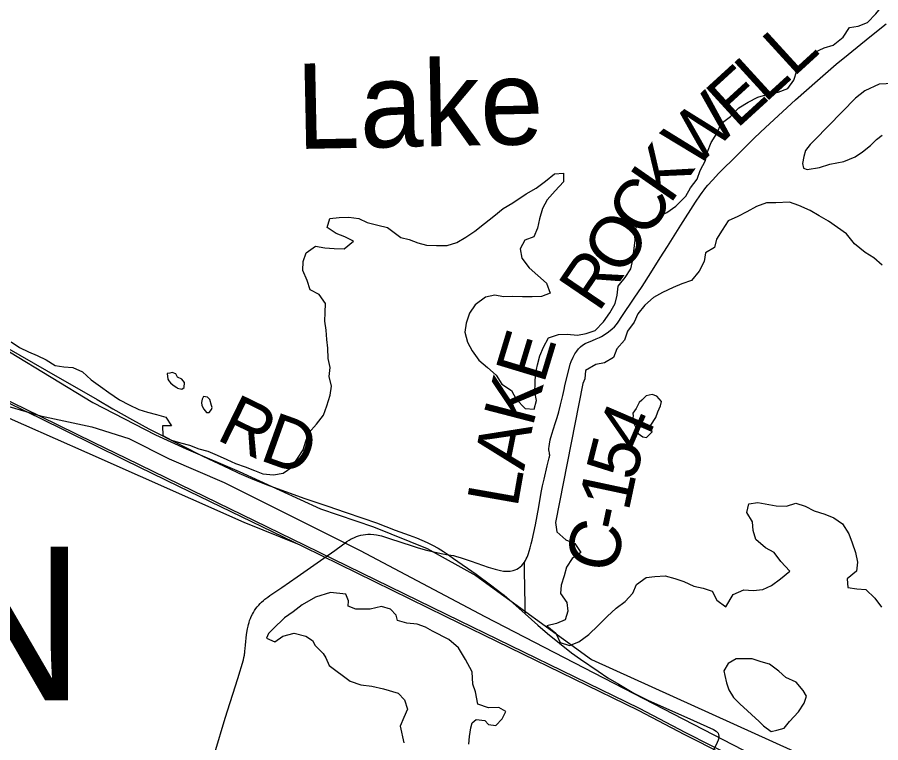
# Model space of a CAD drawing. Extents: x 0 to 34, y 0 to 22.
# Drawn here: x 3.589 to 4.548, y 15.41 to 16.216 of the extents above; entities that cross this region are included whole.
import ezdxf

# ---------------------------------------------------------------- set-up
doc = ezdxf.new("R2010")
doc.units = 0
for name, color, linetype in [('GM_X_County_Road', 7, 'Continuous'), ('GM_X_County_Road_Text', 7, 'Continuous'), ('GM_X_Major_Lake', 7, 'Continuous'), ('GM_X_Major_Lake_Text', 7, 'Continuous'), ('GM_X_Minor_Lake', 7, 'Continuous'), ('GM_X_Rail_Line', 7, 'Continuous'), ('GM_X_Township_Text', 7, 'Continuous')]:
    doc.layers.add(name, color=color, linetype=linetype)

msp = doc.modelspace()

# ---------------------------------------------------------------- linework, layer by layer
at = {"layer": 'GM_X_County_Road'}
for points in [[(4.1526, 15.61105), (4.15363, 15.61258), (4.15456, 15.61446), (4.15551, 15.61639), (4.15624, 15.61823), (4.15708, 15.62034), (4.15796, 15.62323), (4.15905, 15.62683), (4.16011, 15.63126), (4.16107, 15.63526), (4.16471, 15.65223), (4.16849, 15.67234), (4.17126, 15.68827), (4.1727, 15.69559), (4.1744, 15.70299), (4.17801, 15.71785), (4.18021, 15.72664), (4.18048, 15.72792), (4.18076, 15.72969), (4.18061, 15.73095), (4.18043, 15.73241), (4.18015, 15.734), (4.17987, 15.73556), (4.17986, 15.7371), (4.1801, 15.73952), (4.18035, 15.74201), (4.18124, 15.74697), (4.18288, 15.75304), (4.18678, 15.76492), (4.1888, 15.77143), (4.19073, 15.77796), (4.19282, 15.78572), (4.19528, 15.79595), (4.19668, 15.80262), (4.19748, 15.80689), (4.20332, 15.83074), (4.20455, 15.83387), (4.20686, 15.83872), (4.20867, 15.84234), (4.21065, 15.8453), (4.21263, 15.84777), (4.21481, 15.84996), (4.21715, 15.85196), (4.21991, 15.8538), (4.22804, 15.8573), (4.2321, 15.85881), (4.23583, 15.86034), (4.23821, 15.86166), (4.24126, 15.86338), (4.24587, 15.86675), (4.2499, 15.87021), (4.25254, 15.87243), (4.25476, 15.87481), (4.25674, 15.87753), (4.26085, 15.88394), (4.27455, 15.90425), (4.2832, 15.91712), (4.29279, 15.93233), (4.30336, 15.94909), (4.31134, 15.96159), (4.32614, 15.98514), (4.34259, 16.01063), (4.3481, 16.0189), (4.35011, 16.02166), (4.35214, 16.02445), (4.35417, 16.02698), (4.35641, 16.02978), (4.36134, 16.03538), (4.36865, 16.04293), (4.38918, 16.06341), (4.40797, 16.0823), (4.42013, 16.09388), (4.45357, 16.1244), (4.47815, 16.14612), (4.49883, 16.16397), (4.51226, 16.175), (4.53634, 16.19458), (4.55442, 16.20884)], [(3.54324, 15.86873), (3.59242, 15.84076), (3.622, 15.82368), (3.67801, 15.79144), (3.69569, 15.78104), (3.71741, 15.76888), (3.73548, 15.75914), (3.77143, 15.74068), (3.7954, 15.7288), (3.82461, 15.71492), (3.83531, 15.70989), (3.84848, 15.70425), (3.86583, 15.69731), (3.90891, 15.68155), (3.93424, 15.67304), (3.9536, 15.66633), (3.97299, 15.65973), (3.98824, 15.65443), (4.00918, 15.64662), (4.02474, 15.64088), (4.03267, 15.63791), (4.03865, 15.63537), (4.04445, 15.63267), (4.05054, 15.62964), (4.05672, 15.62627), (4.06266, 15.62269), (4.06825, 15.61907)], [(3.84175, 15.50891), (3.84193, 15.51006), (3.84223, 15.51202), (3.84257, 15.51516), (3.84295, 15.51875), (3.84408, 15.53054), (3.84501, 15.53675), (3.84565, 15.53961), (3.8461, 15.54167), (3.84679, 15.54398), (3.84737, 15.54591), (3.84829, 15.54823), (3.84922, 15.55061), (3.85054, 15.55315), (3.85155, 15.55512), (3.85293, 15.55723), (3.85433, 15.55935), (3.85598, 15.56134), (3.85755, 15.56325), (3.85927, 15.56498), (3.86067, 15.56639), (3.86268, 15.56814), (3.86447, 15.5697), (3.86759, 15.57206), (3.86997, 15.57386), (3.88337, 15.58292), (3.90029, 15.59443), (3.92968, 15.61522), (3.94187, 15.62381), (3.95039, 15.63004), (3.95332, 15.63218), (3.95545, 15.63373), (3.95812, 15.63543), (3.96024, 15.63679), (3.96301, 15.6381), (3.96602, 15.63939), (3.96842, 15.64017), (3.97087, 15.64086), (3.97336, 15.64124), (3.97599, 15.64156), (3.9787, 15.64181), (3.98174, 15.64181), (3.98537, 15.64164), (3.9884, 15.64123), (3.99375, 15.64), (3.99948, 15.63842), (4.01885, 15.63187), (4.02474, 15.62997)], [(4.02474, 15.62997), (4.03455, 15.6268), (4.04389, 15.62418), (4.05331, 15.62182), (4.06196, 15.62006), (4.06825, 15.61907)], [(4.06825, 15.61907), (4.07401, 15.61496), (4.09898, 15.59743), (4.11508, 15.58577), (4.12267, 15.57982), (4.12761, 15.57596), (4.12992, 15.57415), (4.13265, 15.57201), (4.13615, 15.56889), (4.14018, 15.5653), (4.15345, 15.55347)], [(4.06825, 15.61907), (4.07382, 15.61822), (4.07722, 15.61736), (4.08108, 15.61611), (4.09337, 15.61194), (4.11247, 15.60538), (4.11998, 15.60311), (4.12593, 15.60161), (4.12953, 15.60095), (4.13311, 15.60072), (4.13666, 15.60096), (4.14018, 15.6017), (4.14239, 15.60245), (4.14434, 15.60326), (4.14613, 15.60429), (4.14799, 15.60569), (4.14976, 15.60731), (4.15128, 15.60908), (4.1526, 15.61105)], [(4.15345, 15.55347), (4.1533, 15.56361), (4.15274, 15.60129), (4.1526, 15.61105)], [(4.15345, 15.55347), (4.16743, 15.54101), (4.17812, 15.53148), (4.20492, 15.51016), (4.21492, 15.50299), (4.23452, 15.48968), (4.24538, 15.48241), (4.2574, 15.47531), (4.27401, 15.46554), (4.29045, 15.45715), (4.32969, 15.43978), (4.34053, 15.43513), (4.36239, 15.4251), (4.36546, 15.42323), (4.36668, 15.42211), (4.3676, 15.42082), (4.36816, 15.41934), (4.36842, 15.41767), (4.36832, 15.41553), (4.36776, 15.41329), (4.36669, 15.41049), (4.36254, 15.40212)], [(3.80881, 15.39899), (3.82031, 15.43773), (3.8345, 15.48148), (3.84048, 15.50234), (3.84102, 15.50504), (3.84157, 15.50776), (3.84175, 15.50891)]]:
    msp.add_lwpolyline(points, dxfattribs=at)
at = {"layer": 'GM_X_Major_Lake'}
for p, q in [((3.76263, 15.80741), (3.76643, 15.80478)), ((4.21754, 15.80942), (4.18696, 15.65484)), ((3.79422, 15.7849), (3.79652, 15.78074)), ((4.28016, 15.78829), (4.27681, 15.78144))]:
    msp.add_line(p, q, dxfattribs=at)
for points in [[(4.49543, 16.1851), (4.50671, 16.19428), (4.51344, 16.20495), (4.52327, 16.20617), (4.53346, 16.21042), (4.54284, 16.21997), (4.55147, 16.23028)], [(4.04375, 15.96317), (4.05511, 15.9625), (4.06684, 15.96259), (4.07742, 15.96608), (4.08759, 15.97185), (4.09737, 15.97875), (4.10829, 15.98718), (4.11844, 15.99522), (4.12897, 16.00365), (4.1399, 16.01018), (4.15458, 16.02015), (4.16551, 16.0263), (4.17604, 16.03397), (4.18582, 16.04239), (4.19604, 16.04285), (4.19611, 16.03337), (4.18673, 16.02343), (4.17772, 16.0135), (4.1725, 16.00361), (4.16918, 15.9922), (4.16699, 15.98195), (4.1629, 15.97244), (4.15309, 15.96857), (4.14787, 15.95905), (4.14984, 15.94845), (4.15787, 15.93789), (4.1674, 15.92924), (4.17693, 15.92097), (4.18118, 15.90963), (4.17137, 15.90614), (4.16115, 15.90568), (4.15056, 15.9056), (4.1392, 15.90589), (4.12936, 15.90581), (4.11988, 15.90764), (4.10931, 15.90528), (4.09802, 15.89685), (4.09166, 15.88732), (4.08796, 15.87629), (4.08652, 15.86642), (4.08926, 15.85545), (4.09463, 15.84563), (4.1019, 15.83545), (4.11143, 15.82718), (4.12134, 15.81853), (4.12747, 15.80872), (4.13812, 15.8016), (4.1435, 15.79178), (4.15342, 15.78162), (4.16327, 15.78094), (4.16584, 15.79044), (4.16425, 15.80028), (4.16455, 15.80977), (4.16486, 15.81963), (4.16704, 15.83027), (4.16961, 15.84014), (4.1737, 15.84966), (4.1793, 15.85994), (4.19025, 15.86381), (4.20008, 15.86427), (4.21145, 15.86322), (4.22127, 15.86481), (4.23109, 15.86831), (4.24047, 15.87786), (4.24759, 15.88777), (4.25318, 15.89806), (4.25576, 15.90756), (4.25682, 15.91742), (4.26431, 15.92696), (4.27067, 15.93687), (4.27286, 15.94675), (4.27392, 15.95661), (4.27572, 15.96838), (4.27488, 15.97862), (4.27935, 15.98813), (4.28919, 15.98783), (4.30088, 15.99399), (4.31068, 15.99937), (4.32084, 16.00628), (4.33173, 16.01736), (4.33696, 16.02688), (4.34445, 16.03641), (4.34778, 16.04592), (4.35375, 16.05696), (4.35594, 16.06684), (4.36003, 16.07711), (4.36638, 16.08702), (4.37122, 16.09806), (4.38137, 16.1061), (4.39076, 16.11565), (4.40093, 16.1218), (4.41186, 16.12757), (4.42319, 16.13069), (4.43453, 16.13305), (4.44509, 16.13693), (4.45183, 16.14646), (4.45516, 16.15672), (4.46416, 16.16627), (4.4743, 16.17697), (4.48561, 16.18237), (4.49543, 16.1851)], [(4.54996, 15.94094), (4.54043, 15.94883), (4.53092, 15.95482), (4.51911, 15.96459), (4.51032, 15.97552), (4.50043, 15.98265), (4.49015, 15.98977), (4.47989, 15.99576), (4.47, 16.00137), (4.45747, 16.00696), (4.44684, 16.01067), (4.43171, 16.01017), (4.42149, 16.01009), (4.41017, 16.00583), (4.39961, 16.00006), (4.38943, 15.99505), (4.37888, 15.99004), (4.37214, 15.97975), (4.36579, 15.96984), (4.36359, 15.96034), (4.3538, 15.95458), (4.35236, 15.94471), (4.34677, 15.93405), (4.33814, 15.92374), (4.32757, 15.92025), (4.31776, 15.916), (4.30607, 15.9106), (4.2959, 15.90483), (4.28613, 15.89641), (4.27863, 15.88688), (4.27454, 15.87737), (4.26705, 15.86745), (4.26372, 15.85756), (4.25509, 15.84801), (4.25138, 15.83813), (4.24159, 15.83236), (4.23176, 15.83039), (4.22046, 15.82385), (4.21978, 15.81437), (4.21754, 15.80942)], [(3.58247, 15.85569), (3.59198, 15.84932), (3.60186, 15.84446), (3.61136, 15.84036), (3.62161, 15.83551), (3.6315, 15.82952), (3.64098, 15.8277), (3.6512, 15.82702), (3.66184, 15.82217), (3.67137, 15.81352), (3.68164, 15.80602), (3.69116, 15.79927), (3.70295, 15.7914), (3.71359, 15.78579), (3.72423, 15.78056), (3.7341, 15.7776), (3.74396, 15.77503), (3.7542, 15.77207), (3.76071, 15.76226), (3.75049, 15.76218), (3.75095, 15.75157), (3.76083, 15.74634), (3.7707, 15.74338), (3.78056, 15.7408), (3.79119, 15.73671), (3.80105, 15.73414), (3.8113, 15.72966), (3.82194, 15.72482), (3.83181, 15.72034), (3.84244, 15.71663), (3.85269, 15.71254), (3.86218, 15.7092), (3.87392, 15.70777), (3.8845, 15.70975), (3.89429, 15.71628), (3.90065, 15.72619), (3.90701, 15.73572), (3.90996, 15.74522), (3.9133, 15.75473), (3.92155, 15.76427), (3.92942, 15.77419), (3.93312, 15.78446), (3.93681, 15.79624), (3.93825, 15.80649), (3.93589, 15.81709), (3.93695, 15.82696), (3.9346, 15.83718), (3.93414, 15.84856), (3.9333, 15.85841), (3.93247, 15.86864), (3.93087, 15.87849), (3.93117, 15.88835), (3.93185, 15.89821), (3.92458, 15.9084), (3.9147, 15.91325), (3.91122, 15.92384), (3.90659, 15.9348), (3.90689, 15.94504), (3.91022, 15.95455), (3.92076, 15.96184), (3.93099, 15.96002), (3.94122, 15.95934), (3.95257, 15.95905), (3.96272, 15.96747), (3.95322, 15.97233), (3.94336, 15.97604), (3.93346, 15.98279), (3.93641, 15.99267), (3.947, 15.99389), (3.9576, 15.99397), (3.96858, 15.99254), (3.97808, 15.98807), (3.98984, 15.98512), (4.00046, 15.98255), (4.0153, 15.97167)], [(4.0153, 15.97167), (4.02478, 15.96947), (4.03427, 15.96575), (4.04375, 15.96317)], [(3.76643, 15.80478), (3.7672, 15.80403), (3.77212, 15.80293), (3.77476, 15.80484), (3.77509, 15.81054), (3.77204, 15.81431), (3.76748, 15.81654), (3.76556, 15.81994), (3.76138, 15.82143), (3.75874, 15.82103), (3.75571, 15.82062), (3.75652, 15.81418), (3.75767, 15.8123), (3.75958, 15.81004), (3.76263, 15.80741)], [(3.79652, 15.78074), (3.79958, 15.77698), (3.80261, 15.777), (3.80523, 15.78043), (3.80597, 15.78271), (3.80519, 15.78498), (3.80325, 15.79141), (3.80058, 15.79405), (3.79603, 15.79477), (3.79484, 15.79181), (3.79385, 15.78819), (3.79422, 15.7849)], [(4.27681, 15.78144), (4.27306, 15.77648), (4.27347, 15.77307), (4.27237, 15.76852), (4.27737, 15.75831), (4.27892, 15.75378), (4.28424, 15.75002), (4.28804, 15.7493), (4.29442, 15.75579), (4.29287, 15.75995), (4.29285, 15.76299), (4.29846, 15.77175), (4.30068, 15.77784), (4.30365, 15.78469), (4.30475, 15.78924), (4.29979, 15.79527), (4.29447, 15.79713), (4.28767, 15.79556), (4.28279, 15.79097), (4.28016, 15.78829)], [(4.18696, 15.65484), (4.18856, 15.64462), (4.19847, 15.63559), (4.20872, 15.6315), (4.21523, 15.62169), (4.20544, 15.61479), (4.19946, 15.60526), (4.19688, 15.59576), (4.19356, 15.58549), (4.1925, 15.57601), (4.19977, 15.5662), (4.20098, 15.55635), (4.19802, 15.54685), (4.18822, 15.5426), (4.17764, 15.54024), (4.18754, 15.53198), (4.19216, 15.52177), (4.20279, 15.51845), (4.21298, 15.52232), (4.22427, 15.53037), (4.23441, 15.54069), (4.24455, 15.55063), (4.25432, 15.5598), (4.26448, 15.56709), (4.27311, 15.57663), (4.2772, 15.58615), (4.28774, 15.59381), (4.29757, 15.59503), (4.30892, 15.59588), (4.31954, 15.59292), (4.32978, 15.58959), (4.3408, 15.58437), (4.35104, 15.58217), (4.3609, 15.57884), (4.36628, 15.56864), (4.37618, 15.56113), (4.3844, 15.57485), (4.39609, 15.58025), (4.40669, 15.57957), (4.41728, 15.58041), (4.42709, 15.58504), (4.43687, 15.59232), (4.4474, 15.60075), (4.43747, 15.61167), (4.42983, 15.62147), (4.42033, 15.6267), (4.40965, 15.6361), (4.40655, 15.64594), (4.40572, 15.65579), (4.39958, 15.66598), (4.40178, 15.67586), (4.41161, 15.67707), (4.43207, 15.67344), (4.44381, 15.67315), (4.454, 15.67626), (4.46425, 15.67293), (4.4745, 15.66808), (4.48627, 15.66438), (4.49614, 15.66028), (4.50565, 15.65353), (4.51293, 15.64221), (4.51642, 15.63238), (4.52029, 15.62179), (4.52264, 15.61081), (4.52121, 15.60094), (4.51105, 15.59252), (4.51189, 15.58267), (4.52174, 15.58123), (4.53158, 15.58055), (4.54188, 15.57077), (4.54915, 15.56097)]]:
    msp.add_lwpolyline(points, dxfattribs=at)
at = {"layer": 'GM_X_Minor_Lake'}
for p, q in [((4.52011, 16.12651), (4.47506, 16.0799)), ((3.93575, 15.49627), (3.95898, 15.47862)), ((4.39178, 15.45355), (4.41313, 15.434))]:
    msp.add_line(p, q, dxfattribs=at)
for points in [[(4.562, 16.14277), (4.54649, 16.14189), (4.53065, 16.13456), (4.52011, 16.12651)], [(4.47506, 16.0799), (4.4698, 16.07493), (4.46456, 16.06806), (4.46272, 16.0616), (4.46126, 16.05363), (4.46244, 16.04871), (4.46661, 16.04722), (4.48022, 16.04923), (4.49193, 16.05311), (4.50742, 16.05588), (4.51987, 16.06129), (4.52815, 16.06666), (4.5368, 16.07393), (4.54356, 16.08043), (4.54996, 16.08541)], [(4.09086, 15.40873), (4.09155, 15.41708), (4.09298, 15.42695), (4.09446, 15.43227), (4.09897, 15.4361), (4.10844, 15.43504), (4.11264, 15.43052), (4.12097, 15.42945), (4.12773, 15.4367), (4.13182, 15.44508), (4.12422, 15.44957), (4.11287, 15.4491), (4.10073, 15.45318), (4.09835, 15.46681), (4.09525, 15.47551), (4.09439, 15.48916), (4.08709, 15.50275), (4.07942, 15.51559), (4.06875, 15.52499), (4.05051, 15.53432), (4.04291, 15.53881), (4.03342, 15.54216), (4.02206, 15.5432), (4.01182, 15.54616), (4.01026, 15.55184), (4.00377, 15.55861), (3.99391, 15.56157), (3.98144, 15.55881), (3.96554, 15.55869), (3.95681, 15.56204), (3.95714, 15.56811), (3.95444, 15.57529), (3.93739, 15.57706), (3.9204, 15.57199), (3.9057, 15.56354), (3.89592, 15.55588), (3.88614, 15.54897), (3.87374, 15.53674), (3.86848, 15.53177), (3.86625, 15.52645), (3.87537, 15.52234), (3.8844, 15.52886), (3.89687, 15.53199), (3.90976, 15.52868), (3.91737, 15.52381), (3.92006, 15.51814), (3.92921, 15.50949), (3.9319, 15.50458), (3.93575, 15.49627)], [(4.41313, 15.434), (4.41809, 15.42911), (4.42646, 15.42273), (4.43288, 15.42429), (4.44119, 15.42663), (4.44681, 15.43388), (4.45695, 15.44458), (4.46331, 15.45411), (4.46589, 15.46209), (4.46206, 15.46851), (4.45442, 15.47756), (4.44302, 15.48277), (4.43502, 15.48992), (4.42474, 15.49742), (4.41564, 15.50001), (4.40539, 15.50334), (4.3876, 15.50358), (4.37894, 15.4982), (4.37408, 15.4902), (4.37526, 15.4849), (4.37684, 15.47695), (4.37955, 15.46901), (4.38491, 15.4607), (4.39178, 15.45355)], [(3.95898, 15.47862), (3.97074, 15.47454), (3.98324, 15.47313), (3.99613, 15.47019), (4.01245, 15.46539), (4.01932, 15.45786), (4.0228, 15.44764), (4.01871, 15.43851), (4.01462, 15.42862), (4.01855, 15.41007)]]:
    msp.add_lwpolyline(points, dxfattribs=at)
at = {"layer": 'GM_X_Rail_Line'}
for points in [[(2.1, 16.12076), (2.19668, 16.09945), (2.38635, 16.05631), (3.44462, 15.82298), (3.54707, 15.79332), (3.61512, 15.77341)], [(3.90281, 15.62996), (3.84149, 15.65487), (3.66706, 15.73228), (3.56102, 15.77914), (3.49443, 15.79722), (3.30043, 15.84736), (3.16644, 15.88025), (2.81873, 15.95834), (2.25975, 16.08), (2.11754, 16.10877)], [(3.58094, 15.84467), (3.67315, 15.78836), (3.74299, 15.75232), (3.77701, 15.73672), (3.83587, 15.71178), (3.92597, 15.66998), (3.98497, 15.65018), (4.04449, 15.62618), (4.09846, 15.59615), (4.22694, 15.50267), (4.51879, 15.37053)], [(4.41426, 15.37679), (4.33083, 15.41918), (4.27943, 15.4461), (4.0651, 15.55069), (3.90791, 15.62748), (3.76882, 15.69512), (3.70976, 15.72398), (3.67365, 15.74142), (3.61429, 15.77076), (3.52046, 15.81611)], [(4.4152, 15.37894), (4.3319, 15.42125), (4.28049, 15.44819), (4.06613, 15.55279), (3.90894, 15.62958), (3.76985, 15.69722), (3.71078, 15.72608), (3.67468, 15.74352), (3.61533, 15.77286), (3.52149, 15.81821)], [(3.61512, 15.77341), (3.67213, 15.76107), (3.71313, 15.74823), (3.75819, 15.72572), (3.81897, 15.69946), (3.97015, 15.62379), (4.10879, 15.55037), (4.42792, 15.38531), (4.45195, 15.37737)]]:
    msp.add_lwpolyline(points, dxfattribs=at)

# ---------------------------------------------------------------- texts
at = {"layer": 'GM_X_County_Road_Text'}
for s, rotation, p in [('L', 42.43252, (4.45096, 16.1488)), ('L', 42.43232, (4.41959, 16.12012)), ('E', 42.42936, (4.38822, 16.09145)), ('W', 43.70089, (4.34087, 16.04619)), ('K', 55.0793, (4.31419, 16.00745)), ('C', 56.92669, (4.28899, 15.96875)), ('O', 56.91152, (4.26168, 15.92684)), ('R', 55.83038, (4.23482, 15.88726)), ('E', 73.14681, (4.17403, 15.80786)), ('K', 75.43628, (4.16162, 15.76004)), ('R', 334.02318, (3.80895, 15.74785)), ('4', 66.67841, (4.28323, 15.73146)), ('D', 340.24457, (3.857, 15.72483)), ('A', 78.6922, (4.15201, 15.71185)), ('5', 75.73402, (4.27537, 15.69979)), ('L', 80.01559, (4.1447, 15.67033)), ('1', 77.96339, (4.2682, 15.66612)), ('-', 78.01576, (4.26336, 15.64331)), ('C', 76.80908, (4.25242, 15.5966))]:
    msp.add_text(s, height=0.05682, rotation=rotation, dxfattribs=at).set_placement(p)
at = {"layer": 'GM_X_Major_Lake_Text'}
msp.add_text('Lake', height=0.094741, rotation=1.17323, dxfattribs=at).set_placement((3.8999, 16.06979))
at = {"layer": 'GM_X_Township_Text'}
msp.add_text('FRANKLIN', height=0.170455, rotation=0.00001, dxfattribs=at).set_placement((2.53713, 15.45751))

doc.saveas('drawing.dxf')
